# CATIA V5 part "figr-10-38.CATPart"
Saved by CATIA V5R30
Part number: Part1
Bounding box of the stored display mesh (mm): x -94.328 to 61.591, y -127.491 to 0, z 0 to 176.047
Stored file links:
  D:\PROJECTS\CATIA V56R 2020\Resources\Parts File\c10_catia_v5_6r2020_prt\figr-10-38.CATPart
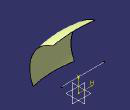
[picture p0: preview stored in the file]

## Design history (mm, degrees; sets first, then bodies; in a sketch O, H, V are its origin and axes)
Body1 (main body)
  Sketch1 on zx-plane, origin (0, 0, 0), H (-1, 0, 0), V (0, 0, 1)
    line L1 (-61.5909, 52.3674) -> (94.3285, 52.3674)
    horizontal: L1 H
  Sketch2 on xy-plane, origin (0, 0, 0), H (1, 0, 0), V (0, 1, 0)
    spline S1 through (-163.8621, -89.1589) (-19.9449, -116.4274) (134.5767, -79.3119)
  Sweep1: type Circle, Guide Sketch1, Reference Sketch2, Radius 100, Angle1 0, Angle2 100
